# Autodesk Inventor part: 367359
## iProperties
Created: 2006-08
Part Number: 367359
Material: 8.8 vz
Description: Senkschraube
Vendor: Autodesk Inc.
Document SubType Name: Modeling
Standard: DIN 7991
Designer: I.Baliuc
Standards Organization: DIN
Language: de-DE
Size Designation: M10 x 20
Categories: <MemberInstance Version="R10.0.0"><Categories><Category DisplayName="Schrauben" InternalName="e4da775c-781d-43d5-af7c-5136215cf5a6" Mnemonic="FSTN"><Category Di
Density: 7.85 g/cm^3
Mass: 15.9991 g
Surface Area: 12.9476 cm^2
Volume: 2.0381 cm^3
Abmessung: M10 x 20
Author: T.Messerschmitt
Comments: DIN 7991 - M10 x 20
Revision Number: 367359
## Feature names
1. Körper [Revolution]
2. Loch [Extrusion]
3. Fase1 [Chamfer]
